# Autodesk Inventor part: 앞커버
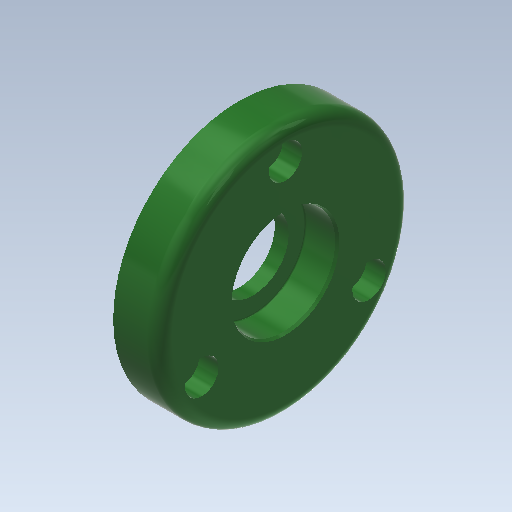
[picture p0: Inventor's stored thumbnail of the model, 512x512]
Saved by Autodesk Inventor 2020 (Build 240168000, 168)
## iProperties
Created: 2015-11
Part Number: 앞커버
Material: 알루미늄 6061
Document SubType Name: Modeling
Designer: mduedu
Density: 1 g/cm^3
Appearance: 매끄러움 - 짙은 산림 녹색
Author: mduedu
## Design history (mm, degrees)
sketch "스케치5"
  geometry: C1 r 30 at (0, 0); 2 further points
  constraints: 2 coincident, 1 centre point
  dimensions: "d66" = 60 diameter of C1
extrude "돌출2" new body sketch "스케치5" distance "d67" = 11; taper "d68" = 0 deg
sketch "스케치6"
  geometry: C1 r 16 at (0, 0); 1 further point
  constraints: 1 centre point, 1 coincident
  dimensions: "d69" = 32 diameter of C1
extrude "돌출3" join sketch "스케치6" distance "d70" = 3; taper "d71" = 0 deg
hole "구멍7" diameter "d98" = 27; stored, may be unused: countersink angle "d102" = 90 deg, drill point angle "d104" = 0 deg; dims "d99" = 6, "d100" = 4, "d101" = 2, "d103" = 3, "d143" = 10, "d144" = 10
hole "구멍8" diameter "d107" = 25; stored, may be unused: countersink angle "d111" = 90 deg, drill point angle "d113" = 0 deg; dims "d105" = 10, "d106" = 10, "d108" = 6, "d109" = 4, "d110" = 2, "d112" = 7.7
hole "구멍9" diameter "d116" = 17; stored, may be unused: countersink angle "d120" = 90 deg, drill point angle "d122" = 0 deg; dims "d114" = 10, "d115" = 10, "d117" = 6, "d118" = 4, "d119" = 2, "d121" = 7.7
chamfer "모따기2" distance "d123" = 0.6; stored, may be unused: second distance "d124" = 2, angle "d125" = 30 deg
fillet "모깎기11" dims "d126" = 0.3
fillet "모깎기13" dims "d128" = 3
fillet "모깎기14" dims "d129" = 3
fillet "모깎기15" dims "d130" = 0.3
sketch "스케치8" dims "d131" = 46
  geometry: 3 further points
  constraints: 2 vertical alignment, 1 coincident, 2 other
hole "구멍10" sketch "스케치8" at (0, 23) diameter "d132" = 4.5; stored, may be unused: countersink angle "d136" = 90 deg, drill point angle "d138" = 0 deg; dims "d133" = 6, "d134" = 8, "d135" = 4.6, "d137" = 7.7
node "솔리드2"
pattern_circular "원형 패턴4" dims angle "d140" = 360 deg
